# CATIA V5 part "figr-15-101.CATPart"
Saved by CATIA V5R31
Part number: Part1
Bounding box of the stored display mesh (mm): x -52.43 to 60.529, y -25.631 to 32.893, z 0 to 4
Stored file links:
  D:\PROJECTS\Project 2021\US EDITION\CATIA V5 6R 2021\Resources\Part Files\c15_catia_v5_6r2021_prt\figr-15-101.CATPart
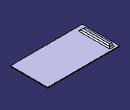
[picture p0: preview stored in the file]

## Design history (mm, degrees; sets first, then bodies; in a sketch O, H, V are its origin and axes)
SheetMetalParameters1: Thickness 1, BendRadius 5, KFactor 0.5 {= log(min(100,max(20*SheetMetalParameters1.BendRadius,SheetMetalParameters1.Thickness)/SheetMetalParameters1.Thickness))/log(100)/2}, ReliefRadialLength 1, ReliefAxialLength 2, MinimumBendRadius 0
Body1 (main body)
  Sketch1 on xy-plane, origin (0, 0, 0), H (1, 0, 0), V (0, 1, 0)
    line L1 (-52.4297, 32.8934) -> (60.5286, 32.8934)
    line L2 (60.5286, 32.8934) -> (60.5286, -25.6312)
    line L3 (60.5286, -25.6312) -> (-52.4297, -25.6312)
    line L4 (-52.4297, -25.6312) -> (-52.4297, 32.8934)
    horizontal: L1 H, L3 H
    vertical: L2 V, L4 V
  Wall1: Thickness 1, Profile Sketch1
  Sketch2 on face of Wall1, origin (0, 0, 1), H (1, 0, 0), V (0, 1, 0)
    line L1 (-47.3159, -16.5837) -> (-43.073, -16.5837)
    line L2 (-43.073, -16.5837) -> (-43.073, 26.788)
    line L3 (-43.073, 26.788) -> (-47.3159, 26.788)
    line L4 (-47.3159, 26.788) -> (-47.3159, -16.5837)
    horizontal: L1 H, L3 H
    vertical: L2 V, L4 V
  d_Stamp1: Stamp_FilletRadius 2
